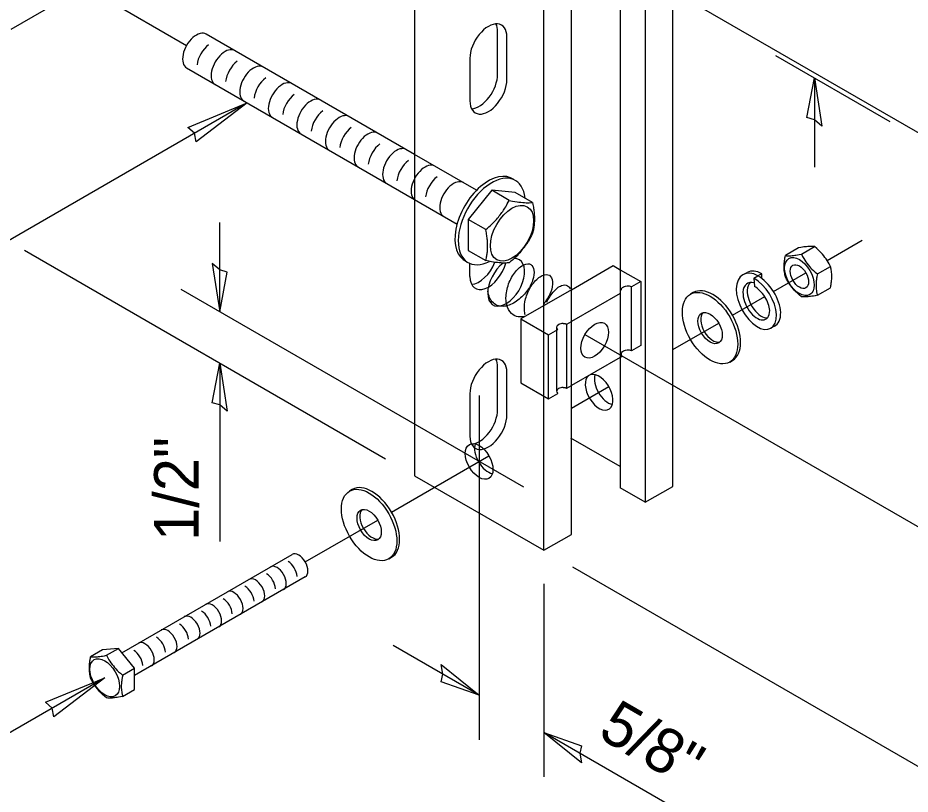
# Model space of a CAD drawing. Extents: x 99862 to 103151, y 100000 to 102076.
# Drawn here: x 101759.1 to 102079.7, y 100232 to 100510.9 of the extents above; entities that cross this region are included whole.
import ezdxf

# ---------------------------------------------------------------- set-up
doc = ezdxf.new("R2010")
doc.units = 0
for name, color, linetype in [('Level 1', 7, 'Continuous'), ('Level 15', 7, 'Continuous'), ('Level 16', 7, 'Continuous'), ('Level 20', 7, 'Continuous'), ('Level 3', 7, 'Continuous'), ('Level 4', 7, 'Continuous'), ('Level 5', 7, 'Continuous'), ('Level 6', 7, 'Continuous'), ('Level 7', 7, 'Continuous'), ('Level 8', 7, 'Continuous')]:
    doc.layers.add(name, color=color, linetype=linetype)

msp = doc.modelspace()

# ---------------------------------------------------------------- linework, layer by layer
at = {"layer": 'Level 1'}
for p, q in [((101901.65, 100836.31), (101901.65, 100346.41)), ((101975.53, 100836.31), (101975.53, 100342.05)), ((101994.46, 100342.6), (101994.46, 100836.31)), ((101984.51, 100830.57), (101984.51, 100336.86)), ((101958, 100325.36), (101958, 100815.26)), ((101948.05, 100319.62), (101948.05, 100809.52)), ((101931.48, 100490.6), (101931.48, 100505.91)), ((101934.8, 100488.68), (101934.8, 100503.99)), ((101921.54, 100496.34), (101921.54, 100481.03)), ((101921.54, 100417.99), (101921.54, 100422.65)), ((101931.48, 100370.15), (101931.48, 100385.46)), ((101934.8, 100368.24), (101934.8, 100383.55)), ((101921.54, 100375.89), (101921.54, 100360.58)), ((101975.53, 100349.7), (101957.82, 100359.93)), ((101901.65, 100346.41), (101948.05, 100319.62)), ((101984.51, 100336.86), (101994.46, 100342.6)), ((101984.51, 100336.86), (101975.53, 100342.05)), ((101948.05, 100319.62), (101958, 100325.36))]:
    msp.add_line(p, q, dxfattribs=at)
for centre, major_axis, start_param, end_param in [((101928.17, 100500.16), (4.69, 8.12), 5.497787, 8.63938), ((101924.85, 100502.08), (-4.69, -8.12), 2.356194, 2.780226), ((101924.85, 100486.77), (-4.69, -8.12), 0.361367, 2.356194), ((101928.17, 100484.86), (4.69, 8.12), 2.356194, 5.497787), ((101928.17, 100421.82), (4.69, 8.12), 2.356194, 5.150172), ((101924.85, 100423.73), (-4.69, -8.12), 0.361367, 1.814656), ((101928.17, 100379.72), (4.69, 8.12), 5.497787, 8.63938), ((101924.85, 100381.63), (-4.69, -8.12), 2.356194, 2.780226), ((101967.94, 100376.4), (3.52, -6.09), 0.252252, 6.533776), ((101971.26, 100378.32), (-3.52, 6.09), 0.490883, 2.65071), ((101928.17, 100364.41), (4.69, 8.12), 2.356194, 5.497787), ((101924.85, 100366.32), (-4.69, -8.12), 0.361367, 2.356194), ((101928.17, 100353.44), (3.52, -6.09), 3.632475, 5.792303)]:
    msp.add_ellipse(centre, major_axis=major_axis, ratio=0.57735, start_param=start_param, end_param=end_param, dxfattribs=at)
msp.add_ellipse((101924.85, 100351.53), major_axis=(3.52, -6.09), ratio=0.57735, dxfattribs=at)
at = {"layer": 'Level 15'}
for p, q in [((102072.54, 100473.54), (102031.42, 100497.28)), ((102045.27, 100489.28), (102045.27, 100457.28)), ((101841.48, 100480.34), (101613.15, 100348.51)), ((101831.65, 100405.34), (101831.65, 100437.35)), ((101891.26, 100352.41), (101761.58, 100427.28)), ((101940.9, 100342.26), (101817.79, 100413.34)), ((101831.65, 100386.82), (101831.65, 100322.82)), ((101924.85, 100375.18), (101924.85, 100251.61)), ((102156.19, 100199.45), (101958.45, 100313.62)), ((101948.05, 100307.62), (101948.05, 100238.22)), ((101924.85, 100267.61), (101893.92, 100285.46)), ((101790.34, 100273.86), (101706.33, 100225.36)), ((102014.81, 100215.68), (101948.05, 100254.22))]:
    msp.add_line(p, q, dxfattribs=at)
for points in [[(102045.27, 100489.28), (102047.95, 100472.01), (102045.27, 100474.28), (102042.6, 100475.1)], [(101841.48, 100480.34), (101823.21, 100466.34), (101822.63, 100469.45), (101820.22, 100471.51)], [(101831.65, 100405.34), (101834.32, 100419.52), (101831.65, 100420.34), (101828.98, 100422.61)], [(101831.65, 100386.82), (101834.32, 100369.55), (101831.65, 100371.82), (101828.98, 100372.64)], [(101924.85, 100267.61), (101911.23, 100272.39), (101911.86, 100275.11), (101911.23, 100278.56)], [(101790.34, 100273.86), (101772.06, 100259.86), (101771.48, 100262.98), (101769.07, 100265.03)], [(101948.05, 100254.22), (101961.68, 100249.44), (101961.04, 100246.72), (101961.68, 100243.27)]]:
    msp.add_lwpolyline(points, close=True, dxfattribs=at)
at = {"layer": 'Level 16'}
for p, q in [((101963.42, 100538.38), (102084.58, 100468.49)), ((101769.77, 100529.86), (101819.79, 100500.99)), ((102049.87, 100423.71), (102062.48, 100430.99)), ((102030.6, 100412.58), (102042.24, 100419.3)), ((102015.85, 100404.06), (102027.43, 100410.75)), ((101994.46, 100391.71), (102010.9, 100401.21)), ((101962.83, 100397.1), (102083.04, 100327.78)), ((101958, 100370.67), (101971.46, 100378.43)), ((101893.36, 100333.35), (101928.37, 100353.56)), ((101862.38, 100315.46), (101888.42, 100330.49))]:
    msp.add_line(p, q, dxfattribs=at)
at = {"layer": 'Level 3'}
for p, q in [((101958, 100413.24), (101972.98, 100421.88)), ((101972.98, 100421.88), (101975.53, 100420.41)), ((101975.53, 100420.41), (101982.92, 100416.14)), ((101982.92, 100416.14), (101979.61, 100414.23)), ((101982.92, 100416.14), (101982.92, 100393.16)), ((101958, 100413.24), (101939.83, 100402.74)), ((101976.59, 100414.09), (101976.53, 100414.06)), ((101979.61, 100391.25), (101979.61, 100414.23)), ((101975.53, 100411.88), (101958, 100401.76)), ((101939.83, 100402.74), (101939.83, 100402.73)), ((101939.83, 100402.73), (101939.83, 100379.78)), ((101939.83, 100402.73), (101949.78, 100396.99)), ((101953.39, 100400.68), (101953.33, 100400.64)), ((101953.33, 100400.64), (101953.39, 100400.68)), ((101956.41, 100400.83), (101958, 100401.76)), ((101956.41, 100377.85), (101956.41, 100400.83)), ((101949.78, 100396.99), (101953.09, 100398.9)), ((101949.78, 100374.04), (101949.78, 100396.99)), ((101952.65, 100399.69), (101952.65, 100376.75)), ((101976.59, 100391.11), (101976.53, 100391.07)), ((101982.92, 100393.16), (101979.61, 100391.25)), ((101975.53, 100388.89), (101958, 100378.78)), ((101975.53, 100388.89), (101976.29, 100389.33)), ((101939.83, 100379.78), (101949.78, 100374.04)), ((101953.39, 100377.73), (101953.33, 100377.7)), ((101953.33, 100377.7), (101953.39, 100377.73)), ((101956.41, 100377.85), (101958, 100378.78)), ((101949.78, 100374.04), (101953.09, 100375.96))]:
    msp.add_line(p, q, dxfattribs=at)
for centre, start_param, end_param in [((101978.17, 100413.11), 5.497787, 6.283185), ((101978.24, 100413.15), 4.082321, 5.497787), ((101954.97, 100399.69), 5.497787, 6.913253), ((101955.04, 100399.73), 4.703695, 5.497787), ((101978.17, 100390.13), 5.497787, 6.913253), ((101978.24, 100390.16), 4.082321, 5.497787), ((101954.97, 100376.75), 5.497787, 6.913253), ((101955.04, 100376.79), 4.703695, 5.497787)]:
    msp.add_ellipse(centre, major_axis=(-2.33, 0), ratio=0.57735, start_param=start_param, end_param=end_param, dxfattribs=at)
msp.add_ellipse((101966.35, 100395.08), major_axis=(3.52, 6.09), ratio=0.57735, dxfattribs=at)
for points in [[(101955.06, 100401.07), (101955.54, 100401.09), (101956.01, 100401), (101956.41, 100400.83)], [(101955.06, 100378.13), (101955.54, 100378.11), (101956.01, 100378.02), (101956.41, 100377.85)]]:
    msp.add_open_spline(points, degree=2, dxfattribs=at)
at = {"layer": 'Level 4'}
for p, q in [((101796.54, 100282.86), (101857.69, 100318.16)), ((101862.38, 100310.04), (101801.05, 100274.64)), ((101789.57, 100283.87), (101785.3, 100281.41)), ((101795.31, 100284.39), (101789.57, 100283.87)), ((101791.05, 100281.93), (101795.31, 100284.39)), ((101801.05, 100277.25), (101795.31, 100284.39)), ((101796.79, 100274.79), (101801.05, 100277.25)), ((101801.05, 100269.59), (101801.05, 100277.25)), ((101796.79, 100267.13), (101801.05, 100269.59))]:
    msp.add_line(p, q, dxfattribs=at)
for centre, start_param, end_param in [((101860.03, 100314.1), 3.141593, 6.283185), ((101852.27, 100309.62), 3.141593, 6.283185), ((101856.15, 100311.86), 4.01075, 5.483611), ((101848.42, 100307.4), 4.01075, 5.483611), ((101844.52, 100305.14), 3.141593, 6.283185), ((101836.75, 100300.66), 3.141593, 6.283185), ((101840.68, 100302.93), 4.01075, 5.483611), ((101832.88, 100298.42), 4.01075, 5.483611), ((101825.12, 100293.95), 4.01075, 5.483611), ((101829, 100296.19), 3.141593, 6.283185), ((101821.29, 100291.74), 3.141593, 6.283185), ((101813.01, 100286.95), 3.141593, 6.283185), ((101817.15, 100289.34), 4.01075, 5.483611), ((101808.91, 100284.59), 4.011039, 5.48392), ((101804.82, 100282.22), 3.141593, 6.283185), ((101800.73, 100279.86), 4.011039, 5.48392)]:
    msp.add_ellipse(centre, major_axis=(-2.34, 4.06), ratio=0.57735, start_param=start_param, end_param=end_param, dxfattribs=at)
msp.add_ellipse((101790.34, 100273.86), major_axis=(3.75, -6.5), ratio=0.57735, dxfattribs=at)
for points in [[(101785.3, 100281.41), (101785.95, 100281.33), (101786.73, 100281.31), (101788.68, 100281.48), (101789.81, 100281.68), (101791.05, 100281.93)], [(101791.05, 100281.93), (101791.7, 100280.59), (101792.47, 100279.29), (101794.42, 100276.87), (101795.56, 100275.79), (101796.79, 100274.79)], [(101785.3, 100273.76), (101785.16, 100274.3), (101785.04, 100274.86), (101784.87, 100276.03), (101784.83, 100276.66), (101784.83, 100277.96), (101784.87, 100278.62), (101785.04, 100280), (101785.16, 100280.71), (101785.3, 100281.41)], [(101791.05, 100266.62), (101789.81, 100267.62), (101788.67, 100268.71), (101786.72, 100271.13), (101785.95, 100272.42), (101785.3, 100273.76)], [(101796.79, 100274.79), (101796.64, 100274.08), (101796.52, 100273.37), (101796.36, 100271.99), (101796.31, 100271.33), (101796.31, 100270.03), (101796.36, 100269.41), (101796.52, 100268.23), (101796.64, 100267.67), (101796.79, 100267.13)], [(101796.79, 100267.13), (101795.55, 100266.88), (101794.41, 100266.69), (101792.46, 100266.51), (101791.69, 100266.53), (101791.05, 100266.62)]]:
    msp.add_open_spline(points, degree=3, dxfattribs=at)
at = {"layer": 'Level 5'}
for p, q in [((102001.78, 100412.18), (102000.79, 100411.61)), ((102014.85, 100387.25), (102015.85, 100387.82)), ((101879.3, 100341.47), (101878.31, 100340.89)), ((101892.37, 100316.53), (101893.36, 100317.11))]:
    msp.add_line(p, q, dxfattribs=at)
for centre, major_axis, start_param, end_param in [((101928.17, 100438.41), (8.51, 14.74), 6.212471, 9.495492), ((101929.37, 100437.72), (8.51, 14.74), 5.605746, 10.143497), ((102008.81, 100400), (-7.03, 12.18), 3.141593, 6.28318), ((102008.81, 100400), (-3.08, 5.33), 0.162038, 2.979555), ((101886.33, 100329.29), (-7.03, 12.18), 3.141593, 6.28318), ((101886.33, 100329.29), (-3.08, 5.33), 0.162038, 2.979555)]:
    msp.add_ellipse(centre, major_axis=major_axis, ratio=0.57735, start_param=start_param, end_param=end_param, dxfattribs=at)
for centre, major_axis in [((102007.82, 100399.43), (-7.03, 12.18)), ((102007.82, 100399.43), (-3.08, 5.33)), ((101885.34, 100328.71), (-7.03, 12.18)), ((101885.34, 100328.71), (-3.08, 5.33))]:
    msp.add_ellipse(centre, major_axis=major_axis, ratio=0.57735, dxfattribs=at)
at = {"layer": 'Level 6'}
for p, q in [((102039.56, 100428.21), (102034.87, 100425.5)), ((102040.61, 100426.01), (102045.3, 100428.72)), ((102019.73, 100418.7), (102021.15, 100419.46)), ((102046.35, 100418.87), (102051.04, 100421.58)), ((102023.58, 100417.32), (102024.99, 100418.22)), ((102023.58, 100417.32), (102023.72, 100414.39)), ((102026.44, 100418.98), (102025.01, 100418.22)), ((102026.38, 100417.33), (102026.44, 100418.98)), ((102046.35, 100411.22), (102051.04, 100413.93)), ((102030.95, 100400.1), (102029.45, 100399.33))]:
    msp.add_line(p, q, dxfattribs=at)
for major_axis in [(3.75, -6.5), (-2.34, 4.06)]:
    msp.add_ellipse((102039.9, 100417.95), major_axis=major_axis, ratio=0.57735, dxfattribs=at)
for centre, major_axis, ratio, start_param, end_param in [((102024.87, 100409.08), (-5.14, 9.62), 0.597856, 5.534976, 7.084707), ((102026.29, 100409.84), (-5.14, 9.62), 0.597856, 5.534976, 6.283185), ((102024.7, 100409.17), (-3.41, 6.37), 0.597856, 5.759529, 7.052859), ((102023.99, 100408.67), (-5.9, 9.18), 0.544801, 3.912787, 5.471187), ((102025.49, 100409.53), (-5.9, 9.18), 0.544801, 3.902515, 5.480817), ((102024.43, 100409.02), (5.01, -9.69), 0.544029, 3.970034, 7.094516), ((102025.93, 100409.8), (-3.32, 6.42), 0.544029, 0.781112, 2.924647), ((102026.21, 100409.88), (-3.41, 6.37), 0.597856, 0.161668, 0.762283), ((102024.14, 100408.59), (-3.9, 6.08), 0.544801, 3.919127, 5.49806), ((102024.43, 100409.02), (-3.32, 6.42), 0.544029, 0.780925, 3.925736), ((102025.93, 100409.8), (5.01, -9.69), 0.544029, 0, 0.811331)]:
    msp.add_ellipse(centre, major_axis=major_axis, ratio=ratio, start_param=start_param, end_param=end_param, dxfattribs=at)
for points in [[(102034.87, 100425.5), (102035.52, 100425.42), (102036.29, 100425.39), (102038.24, 100425.57), (102039.38, 100425.76), (102040.61, 100426.01)], [(102045.3, 100428.72), (102044.65, 100428.81), (102043.88, 100428.83), (102041.94, 100428.65), (102040.79, 100428.46), (102039.56, 100428.21)], [(102040.61, 100426.01), (102041.26, 100424.67), (102042.03, 100423.37), (102043.98, 100420.95), (102045.12, 100419.87), (102046.35, 100418.87)], [(102051.04, 100421.58), (102050.39, 100422.92), (102049.63, 100424.21), (102047.68, 100426.63), (102046.53, 100427.72), (102045.3, 100428.72)], [(102034.87, 100417.85), (102034.72, 100418.38), (102034.6, 100418.94), (102034.44, 100420.12), (102034.39, 100420.75), (102034.39, 100422.04), (102034.44, 100422.71), (102034.6, 100424.08), (102034.72, 100424.79), (102034.87, 100425.5)], [(102051.04, 100413.93), (102051.19, 100414.63), (102051.31, 100415.32), (102051.47, 100416.7), (102051.52, 100417.38), (102051.52, 100418.67), (102051.47, 100419.29), (102051.31, 100420.47), (102051.19, 100421.04), (102051.04, 100421.58)], [(102040.61, 100410.7), (102039.38, 100411.71), (102038.23, 100412.79), (102036.28, 100415.22), (102035.52, 100416.51), (102034.87, 100417.85)], [(102046.35, 100418.87), (102046.2, 100418.16), (102046.08, 100417.45), (102045.92, 100416.08), (102045.87, 100415.41), (102045.87, 100414.12), (102045.92, 100413.49), (102046.09, 100412.31), (102046.21, 100411.75), (102046.35, 100411.22)], [(102046.35, 100411.22), (102045.12, 100410.96), (102043.97, 100410.77), (102042.03, 100410.6), (102041.26, 100410.62), (102040.61, 100410.7)]]:
    msp.add_open_spline(points, degree=3, dxfattribs=at)
at = {"layer": 'Level 7'}
msp.add_ellipse((101934.56, 100415.85), major_axis=(4.69, 8.12), ratio=0.57735, start_param=0.944459, end_param=6.633799, dxfattribs=at)
for points in [[(101941.41, 100403.63), (101941.2, 100403.59), (101940.08, 100403.38), (101937.72, 100403.56), (101935.14, 100405.74), (101934.16, 100410.18), (101935.19, 100415.4), (101937.78, 100419.95), (101940.98, 100422.6), (101943.68, 100422.66), (101944.78, 100420.48), (101944.36, 100416.63), (101942.17, 100412.47), (101938.36, 100408.84), (101934, 100406.75), (101929.6, 100407.85), (101928.16, 100411.01), (101927.95, 100412.71)], [(101941.35, 100404.23), (101941.27, 100404.59), (101941.05, 100405.96), (101941.22, 100409.7), (101943.35, 100414.82), (101946.85, 100418.36), (101949.77, 100419.06), (101951.43, 100417.16), (101951.15, 100413.32), (101949.47, 100409.97), (101948.18, 100408.31), (101947.95, 100408.04)], [(101949.16, 100408.72), (101949.61, 100409.71), (101951.28, 100412.59), (101954.55, 100415.21), (101956.79, 100414.81), (101957.41, 100413.85), (101957.54, 100413.55)]]:
    msp.add_open_spline(points, degree=3, dxfattribs=at)
at = {"layer": 'Level 8'}
for p, q in [((101756.71, 100506.78), (101789.86, 100525.92)), ((101901.65, 100461.84), (101826.82, 100505.05)), ((101819.79, 100492.87), (101901.65, 100445.6)), ((101923.93, 100448.98), (101901.65, 100461.84)), ((101929.37, 100448.93), (101920.96, 100438.47)), ((101937.77, 100448.18), (101929.37, 100448.93)), ((101935.61, 100445.32), (101929.37, 100448.93)), ((101901.65, 100445.6), (101916.9, 100436.8)), ((101944.01, 100444.57), (101937.77, 100448.18)), ((101920.96, 100438.47), (101920.96, 100427.26)), ((101927.2, 100434.87), (101920.96, 100438.47)), ((101920.96, 100427.26), (101927.2, 100423.66))]:
    msp.add_line(p, q, dxfattribs=at)
for centre, major_axis, start_param, end_param in [((101823.3, 100498.96), (-3.52, -6.09), 3.141593, 6.283191), ((101828.43, 100496), (3.52, 6.08), 0.942075, 2.218001), ((101833.56, 100493.03), (3.52, 6.08), 0, 3.141593), ((101838.69, 100490.06), (3.52, 6.08), 0.942075, 2.218001), ((101843.82, 100487.11), (3.52, 6.08), 0, 3.141593), ((101848.94, 100484.12), (3.52, 6.08), 0.942075, 2.218001), ((101854.09, 100481.18), (3.52, 6.08), 0, 3.141593), ((101859.2, 100478.18), (3.52, 6.08), 0.942075, 2.218001), ((101864.35, 100475.26), (3.52, 6.08), 0, 3.141593), ((101869.45, 100472.24), (3.52, 6.08), 0.942075, 2.218001), ((101874.6, 100469.34), (3.52, 6.08), 0, 3.141593), ((101879.71, 100466.3), (3.52, 6.08), 0.942075, 2.218001), ((101884.88, 100463.4), (3.52, 6.08), 0, 3.141593), ((101889.96, 100460.36), (3.52, 6.08), 0.942075, 2.218001), ((101895.13, 100457.49), (3.52, 6.08), 0, 3.141593), ((101900.22, 100454.43), (3.52, 6.08), 0.942075, 2.218001), ((101905.4, 100451.55), (3.52, 6.08), 0, 3.141593), ((101910.53, 100448.59), (3.52, 6.09), 0.942075, 2.218001), ((101915.66, 100445.62), (3.52, 6.09), 0, 3.141593)]:
    msp.add_ellipse(centre, major_axis=major_axis, ratio=0.57735, start_param=start_param, end_param=end_param, dxfattribs=at)
msp.add_ellipse((101936.65, 100433.52), major_axis=(5.49, 9.51), ratio=0.57735, dxfattribs=at)
for points in [[(101927.2, 100434.87), (101929.01, 100436.33), (101930.68, 100437.93), (101933.53, 100441.48), (101934.66, 100443.37), (101935.61, 100445.32)], [(101935.61, 100445.32), (101937.41, 100444.95), (101939.09, 100444.67), (101941.94, 100444.42), (101943.06, 100444.45), (101944.01, 100444.57)], [(101944.01, 100444.57), (101944.22, 100443.54), (101944.4, 100442.52), (101944.64, 100440.52), (101944.71, 100439.52), (101944.71, 100437.63), (101944.64, 100436.72), (101944.4, 100434.99), (101944.23, 100434.16), (101944.01, 100433.37)], [(101927.2, 100423.66), (101927.41, 100424.45), (101927.59, 100425.28), (101927.83, 100427.02), (101927.9, 100427.92), (101927.9, 100429.81), (101927.83, 100430.81), (101927.59, 100432.82), (101927.41, 100433.84), (101927.2, 100434.87)], [(101944.01, 100433.37), (101943.06, 100431.41), (101941.93, 100429.5), (101939.07, 100425.95), (101937.41, 100424.38), (101935.61, 100422.91)], [(101935.61, 100422.91), (101934.66, 100422.79), (101933.52, 100422.76), (101930.67, 100423.01), (101929, 100423.29), (101927.2, 100423.66)]]:
    msp.add_open_spline(points, degree=3, dxfattribs=at)

# ---------------------------------------------------------------- texts
at = {"layer": 'Level 20'}
for s, rotation, p in [('1/2"', 90.0001, (101824.08, 100322.99)), ('5/8"', 330.0064, (101966.96, 100252.74))]:
    msp.add_text(s, height=16, rotation=rotation, dxfattribs=at).set_placement(p)

doc.saveas('drawing.dxf')
